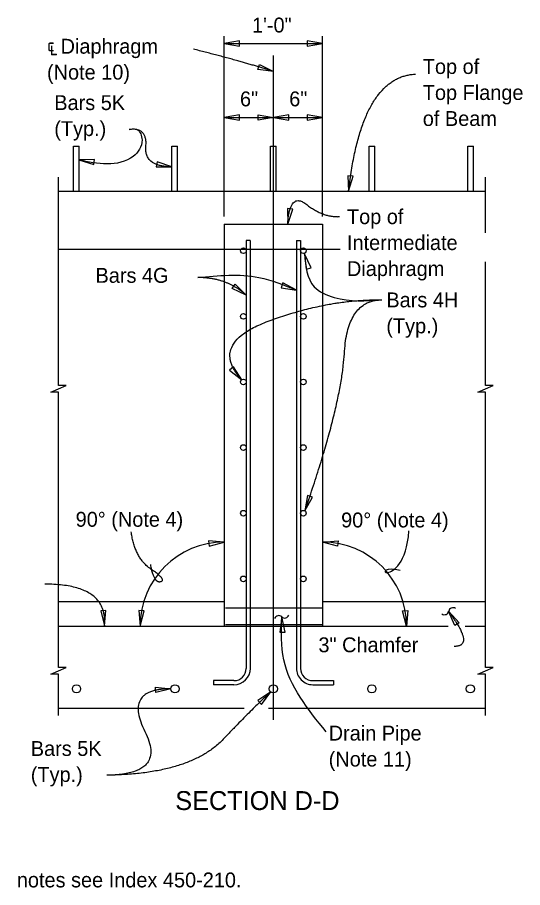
# Model space of a CAD drawing. Extents: x 0.4 to 30.8, y 0.6 to 19.4.
# Drawn here: x 10.56 to 15.7, y 3.36 to 12.2 of the extents above; entities that cross this region are included whole.
import ezdxf

# ---------------------------------------------------------------- set-up
doc = ezdxf.new("R2010")
doc.units = 0
for name, color, linetype in [('BeamConc', 7, 'Continuous'), ('BeamConc_h', 7, 'Continuous'), ('CL_Major', 7, 'Continuous'), ('Dimension', 7, 'Continuous'), ('Miscellaneous', 7, 'Continuous'), ('Rebar', 7, 'Continuous'), ('TextStructures', 7, 'Continuous')]:
    doc.layers.add(name, color=color, linetype=linetype)

msp = doc.modelspace()

# ---------------------------------------------------------------- linework, layer by layer
at = {"layer": 'BeamConc'}
for p, q in [((10.9822, 10.4331), (15.3192, 10.4331)), ((12.6646, 10.0997), (12.6646, 6.0164)), ((12.6646, 10.0997), (13.6646, 10.0997)), ((13.6646, 10.0997), (13.6646, 6.0164)), ((10.9822, 6.2664), (12.6646, 6.2664)), ((13.6646, 6.2664), (15.3192, 6.2664)), ((10.9822, 6.0164), (14.9415, 6.0164)), ((15.1114, 6.0164), (15.3192, 6.0164)), ((10.9822, 5.1831), (12.8689, 5.1831)), ((13.1163, 5.1831), (15.3192, 5.1831))]:
    msp.add_line(p, q, dxfattribs=at)
at = {"layer": 'BeamConc_h'}
msp.add_line((10.9822, 9.8447), (13.8436, 9.8447), dxfattribs=at)
at = {"layer": 'CL_Major'}
msp.add_line((13.1646, 5.0647), (13.1646, 11.8123), dxfattribs=at)
at = {"layer": 'Dimension'}
for p, q in [((12.6646, 10.1753), (12.6646, 12.0087)), ((13.6646, 10.1753), (13.6646, 12.0087)), ((12.6646, 11.9331), (13.6646, 11.9331)), ((12.6646, 11.1831), (13.6646, 11.1831))]:
    msp.add_line(p, q, dxfattribs=at)
for points in [[(12.6647, 11.9331), (12.8208, 11.9066), (12.8208, 11.9595)], [(13.6646, 11.9331), (13.5084, 11.9595), (13.5084, 11.9066)], [(13.1649, 11.6502), (13.0075, 11.6685), (13.0223, 11.7193)], [(12.6647, 11.1831), (12.8208, 11.1566), (12.8208, 11.2095)], [(13.1646, 11.1831), (13.0084, 11.1566), (13.0084, 11.2095)], [(13.1646, 11.1831), (13.3208, 11.1566), (13.3208, 11.2095)], [(13.6646, 11.1831), (13.5084, 11.2095), (13.5084, 11.1566)], [(11.1892, 10.7519), (11.34, 10.7034), (11.3476, 10.7557)], [(11.1892, 10.7519), (11.1897, 10.7517), (11.1897, 10.7519)], [(12.1336, 10.68), (11.9843, 10.7329), (11.9752, 10.6808)], [(13.929, 10.433), (13.9734, 10.5851), (13.9209, 10.5912)], [(13.3097, 10.0997), (13.3607, 10.2497), (13.3084, 10.2582)], [(13.4803, 9.7983), (13.4988, 9.641), (13.5496, 9.6558)], [(12.8889, 9.3768), (12.7456, 9.4442), (12.7758, 9.4877)], [(13.3988, 9.4274), (13.2595, 9.5027), (13.2424, 9.4526)], [(12.8434, 8.5174), (12.7578, 8.6507), (12.7187, 8.6151)], [(13.4841, 7.1856), (13.5605, 7.3244), (13.5105, 7.3418)], [(12.6645, 6.8698), (12.507, 6.8822), (12.5119, 6.829)], [(13.6646, 6.8698), (13.822, 6.8822), (13.8171, 6.829)], [(11.4487, 6.0165), (11.463, 6.1743), (11.4103, 6.1702)], [(11.811, 6.0163), (11.8518, 6.1689), (11.7987, 6.1738)], [(13.2499, 6.1096), (13.231, 5.9523), (13.2838, 5.9549)], [(14.5181, 6.0163), (14.4773, 6.1689), (14.5304, 6.1738)], [(14.9448, 6.1669), (15.051, 6.0494), (15.0064, 6.0209)], [(12.1234, 5.3777), (11.9693, 5.3409), (11.9657, 5.3937)], [(13.1377, 5.3472), (13.0064, 5.2585), (13.0429, 5.2202)]]:
    msp.add_lwpolyline(points, close=True, dxfattribs=at)
for points in [[(10.9822, 6.0164), (10.9822, 8.392), (10.9047, 8.392), (10.9822, 8.4257), (11.0597, 8.4595), (10.9822, 8.4595), (10.9822, 10.5748)], [(15.3192, 10.009), (15.3192, 10.5748)], [(15.3192, 6.0164), (15.3192, 8.392), (15.2417, 8.392), (15.3192, 8.4257), (15.3967, 8.4595), (15.3192, 8.4595), (15.3192, 9.7159)], [(10.9822, 5.1074), (10.9822, 5.5273), (10.9047, 5.5273), (10.9822, 5.561), (11.0597, 5.5948), (10.9822, 5.5948), (10.9822, 6.0164)], [(15.3192, 5.1074), (15.3192, 5.5273), (15.2417, 5.5273), (15.3192, 5.561), (15.3967, 5.5948), (15.3192, 5.5948), (15.3192, 6.0164)]]:
    msp.add_lwpolyline(points, dxfattribs=at)
for centre, radius, start, end in [((12.6646, 6.0164), 0.8535, 90, 180), ((13.6646, 6.0164), 0.8535, 0, 90), ((14.9891, 6.158), 0.0447, 56.58686, 168.31408), ((13.2188, 6.0769), 0.0447, 46.94989, 158.67711), ((13.2798, 6.1422), 0.0447, 226.94989, 338.67711), ((14.9015, 6.1761), 0.0447, 236.58686, 348.31408)]:
    msp.add_arc(centre, radius, start, end, dxfattribs=at)
for points, degree in [([(13.1646, 11.6508), (12.7985, 11.7648), (12.353, 11.8758)], 2), ([(13.929, 10.4331), (14.059, 11.5973), (14.6082, 11.6229)], 2), ([(12.1336, 10.68), (11.8528, 10.6838), (11.8866, 11.0848), (11.6993, 11.0598)], 2), ([(13.3097, 10.0997), (13.33, 10.4331), (13.6713, 10.166), (13.8369, 10.1753)], 2), ([(12.8887, 9.3775), (12.692, 9.5557), (12.3955, 9.5568)], 2), ([(12.8434, 8.5174), (12.5059, 8.888), (13.723, 9.3385), (14.2675, 9.3296)], 2), ([(13.4841, 7.1856), (13.8566, 8.2544), (13.916, 9.3286), (14.2675, 9.3296)], 2), ([(11.9154, 6.6398), (11.9464, 6.4534), (12.0872, 6.4811), (11.7565, 6.7057), (11.7196, 6.9743)], 2), ([(14.4531, 6.5795), (14.2971, 6.6232), (14.242, 6.4811), (14.5185, 6.6534), (14.542, 6.9825)], 3), ([(11.4484, 6.0164), (11.4889, 6.4417), (10.8425, 6.4417)], 2), ([(14.9697, 6.1278), (15.2049, 5.8089), (15.0006, 5.8089)], 2), ([(12.1233, 5.3777), (11.6388, 5.3806), (12.0821, 4.5055), (11.4722, 4.5005)], 2), ([(13.1377, 5.3472), (12.9904, 5.217), (12.3147, 4.5104), (11.4722, 4.5005)], 2)]:
    msp.add_open_spline(points, degree=degree, dxfattribs=at)
for points in [[(11.6993, 11.0598), (11.7796, 11.0598), (11.8301, 10.9537), (11.7411, 10.7875), (11.477, 10.7103), (11.1892, 10.7519)], [(13.4803, 9.7983), (13.5784, 9.4631), (13.7805, 9.3538), (14.2675, 9.3296)], [(12.3955, 9.5568), (13.0182, 9.5568), (13.3988, 9.4274)], [(13.7004, 4.9411), (13.271, 5.6732), (13.2498, 6.1096)]]:
    msp.add_spline(points, degree=3, dxfattribs=at)
at = {"layer": 'Miscellaneous'}
for p, q in [((12.6775, 6.2), (13.6646, 6.2)), ((12.6775, 6.0323), (13.6646, 6.0323))]:
    msp.add_line(p, q, dxfattribs=at)
at = {"layer": 'Rebar'}
for p, q in [((11.1334, 10.4331), (11.1334, 10.8914)), ((11.1334, 10.8914), (11.1907, 10.8914)), ((11.1907, 10.4331), (11.1907, 10.8914)), ((12.1336, 10.4331), (12.1336, 10.8914)), ((12.1336, 10.8914), (12.191, 10.8914)), ((12.191, 10.4331), (12.191, 10.8914)), ((13.1359, 10.4331), (13.1359, 10.8914)), ((13.1359, 10.8914), (13.1933, 10.8914)), ((13.1933, 10.4331), (13.1933, 10.8914)), ((14.1385, 10.4331), (14.1385, 10.8914)), ((14.1385, 10.8914), (14.1959, 10.8914)), ((14.1959, 10.4331), (14.1959, 10.8914)), ((15.1385, 10.4331), (15.1385, 10.8914)), ((15.1385, 10.8914), (15.1959, 10.8914)), ((15.1959, 10.4331), (15.1959, 10.8914)), ((12.8887, 9.9331), (12.8887, 5.5864)), ((12.9303, 9.9331), (12.8887, 9.9331)), ((12.9303, 9.9331), (12.9303, 5.5842)), ((13.3989, 9.9331), (13.3989, 5.5842)), ((13.3989, 9.9331), (13.4406, 9.9331)), ((13.4406, 9.9331), (13.4406, 5.5864)), ((12.5553, 5.4614), (12.5553, 5.4197)), ((12.7637, 5.4614), (12.5553, 5.4614)), ((12.7636, 5.4197), (12.5553, 5.4197)), ((13.5656, 5.4614), (13.7739, 5.4614)), ((13.5656, 5.4197), (13.7739, 5.4197)), ((13.7739, 5.4614), (13.7739, 5.4197))]:
    msp.add_line(p, q, dxfattribs=at)
for centre, radius in [((12.86, 9.8289), 0.0287), ((13.4692, 9.8288), 0.0287), ((12.86, 9.1622), 0.0287), ((13.4692, 9.1622), 0.0287), ((12.86, 8.4955), 0.0287), ((13.4692, 8.4955), 0.0287), ((12.86, 7.8288), 0.0287), ((13.4692, 7.8288), 0.0287), ((12.86, 7.1621), 0.0287), ((13.4692, 7.1621), 0.0287), ((12.86, 6.4954), 0.0287), ((13.4692, 6.4954), 0.0287), ((11.1646, 5.3784), 0.0413), ((12.1646, 5.3784), 0.0413), ((13.1646, 5.3784), 0.0413), ((14.1646, 5.3784), 0.0413), ((15.1646, 5.3784), 0.0413)]:
    msp.add_circle(centre, radius, dxfattribs=at)
for centre, radius, start, end in [((12.7637, 5.5864), 0.125, 270, 0), ((12.7637, 5.5864), 0.1667, 270, 360), ((13.5656, 5.5864), 0.1667, 179.24004, 270), ((13.5656, 5.5864), 0.125, 180, 270)]:
    msp.add_arc(centre, radius, start, end, dxfattribs=at)

# ---------------------------------------------------------------- texts
at = {"layer": 'Dimension'}
for s, p in [('Top of', (14.6822, 11.6242)), ('Top Flange', (14.6822, 11.3602)), ('Bars 5K', (10.9389, 11.2576)), ('of Beam', (14.6822, 11.0962)), ('(Typ.)', (10.9389, 10.9936)), ('Top of', (13.9121, 10.0993)), ('Intermediate', (13.9121, 9.8353)), ('Diaphragm', (13.9121, 9.5713)), ('Bars 4H', (14.3121, 9.2536)), ('(Typ.)', (14.3121, 8.9896)), ('Drain Pipe', (13.7265, 4.8529)), ('Bars 5K', (10.7003, 4.6965)), ('(Note 11)', (13.7265, 4.5889)), ('(Typ.)', (10.7003, 4.4325))]:
    msp.add_text(s, height=0.1512, dxfattribs=at).set_placement(p)
at = {"layer": 'TextStructures'}
for s, height, p in [('1\'-0"', 0.1512, (12.9475, 12.0455)), ('℄ Diaphragm', 0.1512, (10.865, 11.8301)), ('(Note 10)', 0.1512, (10.865, 11.5671)), ('6"', 0.1512, (12.8251, 11.2955)), ('6"', 0.1512, (13.3253, 11.2955)), ('Bars 4G', 0.1512, (11.3578, 9.5027)), ('90° (Note 4)', 0.1512, (11.1559, 7.0246)), ('90° (Note 4)', 0.1512, (13.8527, 7.0179)), ('3" Chamfer', 0.1512, (13.6219, 5.7497)), ('SECTION D-D', 0.192, (12.1677, 4.147)), ('For referenced notes see Index 450-210.', 0.1512, (9.1763, 3.3612))]:
    msp.add_text(s, height=height, dxfattribs=at).set_placement(p)

doc.saveas('drawing.dxf')
